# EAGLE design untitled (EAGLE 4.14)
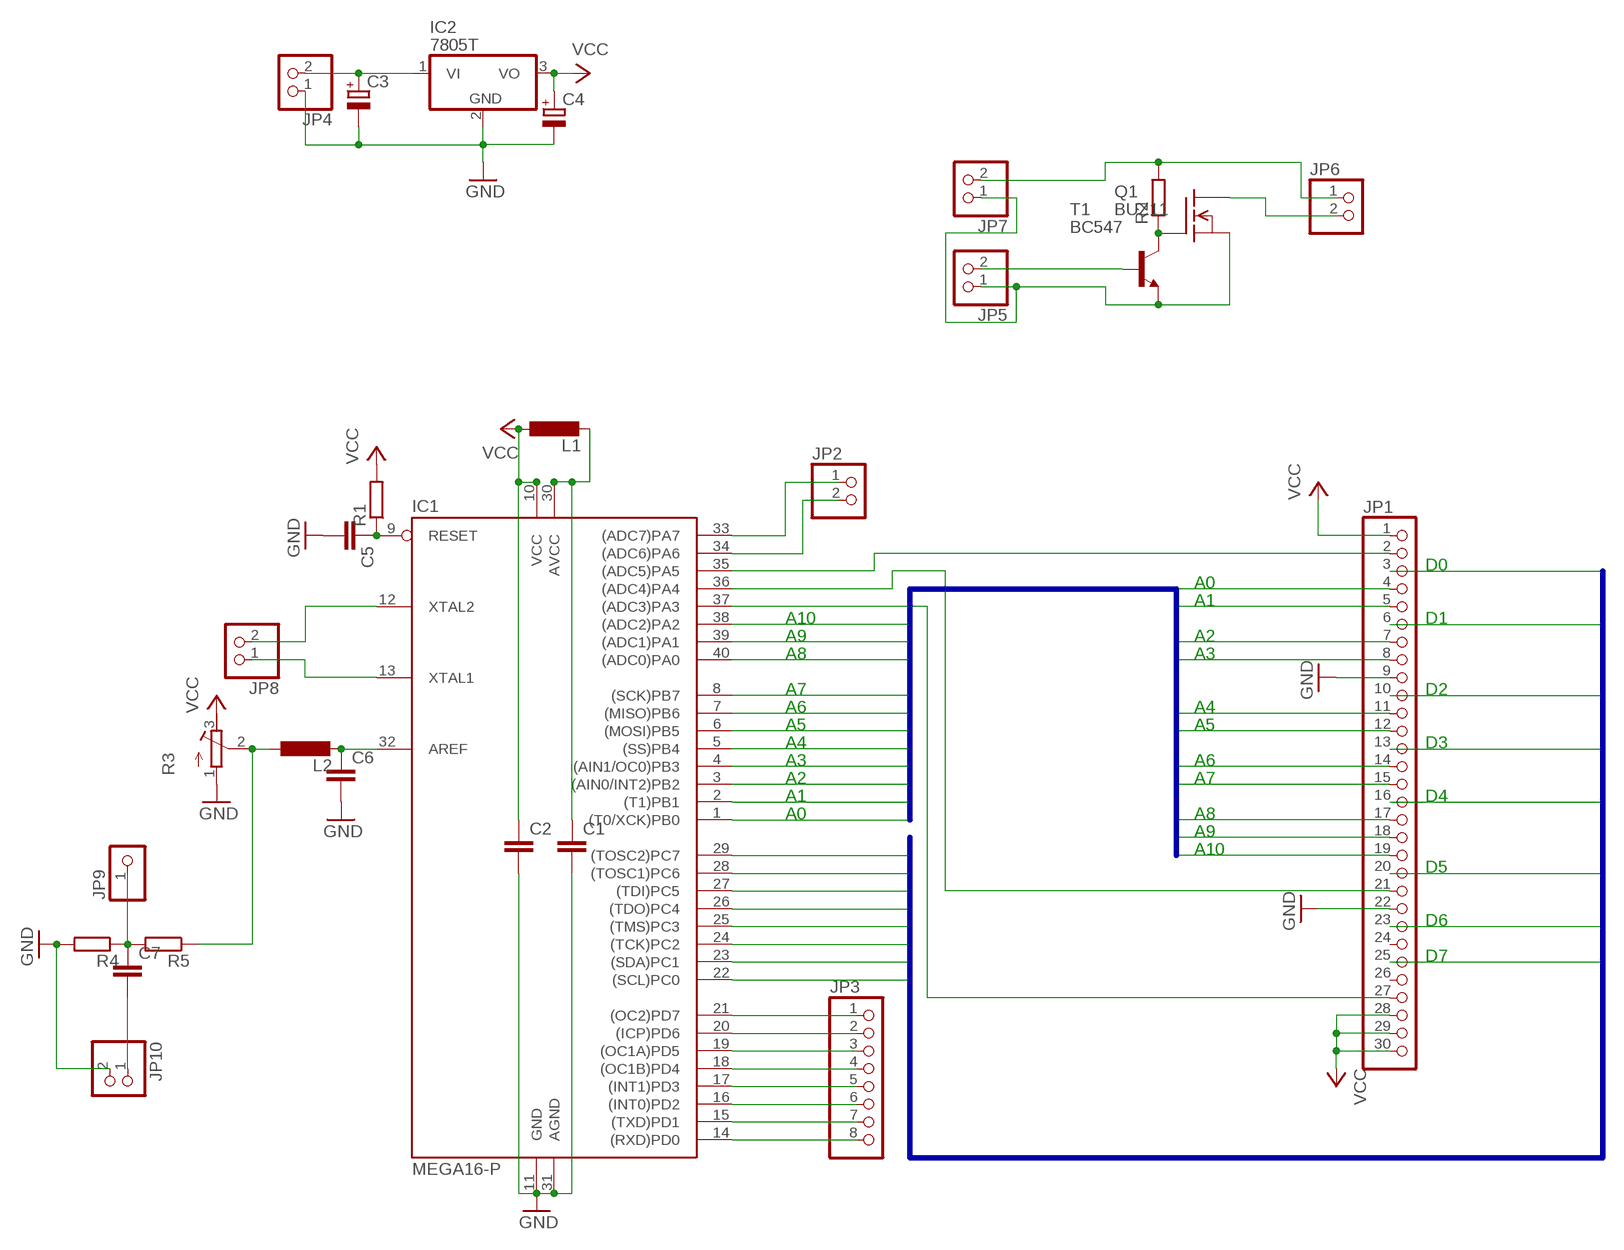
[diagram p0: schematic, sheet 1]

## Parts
C1  C-EU025-025X050  [C025-025X050]
C2  C-EU025-025X050  [C025-025X050]
C3  CPOL-EUE2-4  [E2-4]
C4  CPOL-EUE2-4  [E2-4]
C5  C-EU025-025X050  [C025-025X050]
C6  C-EU025-025X050  [C025-025X050]
C7  C-EU025-025X050  [C025-025X050]
IC1  MEGA16-P  [DIL40]
IC2  7805T  [TO220H]
JP1  PINHD-1X30  [1X30]
JP2  PINHD-1X2  [1X02]
JP3  PINHD-1X8  [1X08]
JP4  PINHD-1X2  [1X02]
JP5  PINHD-1X2  [1X02]
JP6  PINHD-1X2  [1X02]
JP7  PINHD-1X2  [1X02]
JP8  PINHD-1X2  [1X02]
JP9  PINHD-1X1  [1X01]
JP10  PINHD-1X2  [1X02]
L1  L-EUL3225M  [L3225M]
L2  L-EUL3225M  [L3225M]
Q1  BUZ11  [TO220]
R1  R-EU_0207/2V  [0207/2V]
R2  R-EU_0204/7  [0204/7]
R3  R-TRIMM3339P  [RTRIM3339P]
R4  R-EU_0204/7  [0204/7]
R5  R-EU_0204/7  [0204/7]
T1  BC547  [TO92]

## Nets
GND: C1.2 C2.2 C3.- C4.- C5.2 C6.2 IC1.11(GND) IC1.31(AGND) IC2.2(GND) JP1.9 JP1.22 JP4.1 JP10.2 R3.1(E) R4.2
N$1: IC1.22((SCL)PC0) JP1.3
N$2: IC1.23((SDA)PC1) JP1.6
N$3: IC1.24((TCK)PC2) JP1.10
N$4: IC1.25((TMS)PC3) JP1.13
N$5: IC1.26((TDO)PC4) JP1.16
N$6: IC1.27((TDI)PC5) JP1.20
N$7: IC1.28((TOSC1)PC6) JP1.23
N$8: IC1.29((TOSC2)PC7) JP1.25
N$9: IC1.1((T0/XCK)PB0) JP1.4
N$10: IC1.2((T1)PB1) JP1.5
N$11: IC1.3((AIN0/INT2)PB2) JP1.7
N$12: IC1.4((AIN1/OC0)PB3) JP1.8
N$13: IC1.5((SS)PB4) JP1.11
N$14: IC1.6((MOSI)PB5) JP1.12
N$15: IC1.7((MISO)PB6) JP1.14
N$16: IC1.8((SCK)PB7) JP1.15
N$17: IC1.40((ADC0)PA0) JP1.17
N$18: IC1.39((ADC1)PA1) JP1.18
N$19: IC1.38((ADC2)PA2) JP1.19
N$20: IC1.35((ADC5)PA5) JP1.2
N$21: IC1.36((ADC4)PA4) JP1.21
N$22: IC1.34((ADC6)PA6) JP2.2
N$23: IC1.37((ADC3)PA3) JP1.27
N$24: IC1.33((ADC7)PA7) JP2.1
N$25: IC1.21((OC2)PD7) JP3.1
N$26: IC1.20((ICP)PD6) JP3.2
N$27: IC1.19((OC1A)PD5) JP3.3
N$28: IC1.18((OC1B)PD4) JP3.4
N$29: IC1.17((INT1)PD3) JP3.5
N$30: IC1.16((INT0)PD2) JP3.6
N$31: JP6.1 JP7.2 R2.2
N$32: IC1.12(XTAL2) JP8.2
N$33: C1.1 IC1.30(AVCC) L1.2
N$34: JP6.2 Q1.2(D)
N$35: IC1.15((TXD)PD1) JP3.7
N$36: IC1.14((RXD)PD0) JP3.8
N$37: C3.+ IC2.1(VI) JP4.2
N$38: IC1.13(XTAL1) JP8.1
N$39: C5.1 IC1.9(RESET) R1.1
N$40: Q1.1(G) R2.1 T1.3(C)
N$41: JP5.2 T1.2(B)
N$42: JP5.1 JP7.1 Q1.3(S) T1.1(E)
N$43: C6.1 IC1.32(AREF) L2.2
N$44: L2.1 R3.2(S) R5.1
N$45: C7.1 JP9.1 R4.1 R5.2
N$46: C7.2 JP10.1
VCC: C2.1 C4.+ IC1.10(VCC) IC2.3(VO) JP1.1 JP1.28 JP1.29 JP1.30 L1.1 R1.2 R3.3(A)
Unconnected: JP1.24 JP1.26

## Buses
B$2
B$1

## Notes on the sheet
- D0
- A0
- A1
- A10 | D1
- A9 | A2
- A8 | A3
- A7 | D2
- A6 | A4
- A5 | A5
- A4 | D3
- A3 | A6
- A2 | A7
- A1 | D4
- A0 | A8
- A9
- A10
- D5
- D6
- D7

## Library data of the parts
C1 C2 C5-C7 = rcl:C-EU: CAPACITOR, European symbol
C3 C4 = rcl:CPOL-EU: POLARIZED CAPACITOR, European symbol
IC1 = atmel:MEGA16-P: MICROCONTROLLER 16 Kbytes FLASH 1 kbytes SRAM 512 bytes EEPROM USART 8-channel 10 bit ADC
IC2 = linear:78*: Positive VOLTAGE REGULATOR Source: http://cache.national.com/ds/LM/LM78L05.pdf http://www.fairchildsemi.com/ds/LM/LM7805.pdf
JP1 = pinhead:PINHD-1X30: PIN HEADER
JP2 JP4-JP8 JP10 = pinhead:PINHD-1X2: PIN HEADER
JP3 = pinhead:PINHD-1X8: PIN HEADER
JP9 = pinhead:PINHD-1X1: PIN HEADER
L1 L2 = rcl:L-EU: INDUCTOR, European symbol
Q1 = transistor-fet:BUZ11: N-Channel Enhancement MOSFET 50V; 30A; 0,040Ohm
R1 R2 R4 R5 = rcl:R-EU_: RESISTOR, European symbol
R3 = rcl:R-TRIMM: Trimm resistor
T1 = transistor:BC547: NPN TRANSISTOR

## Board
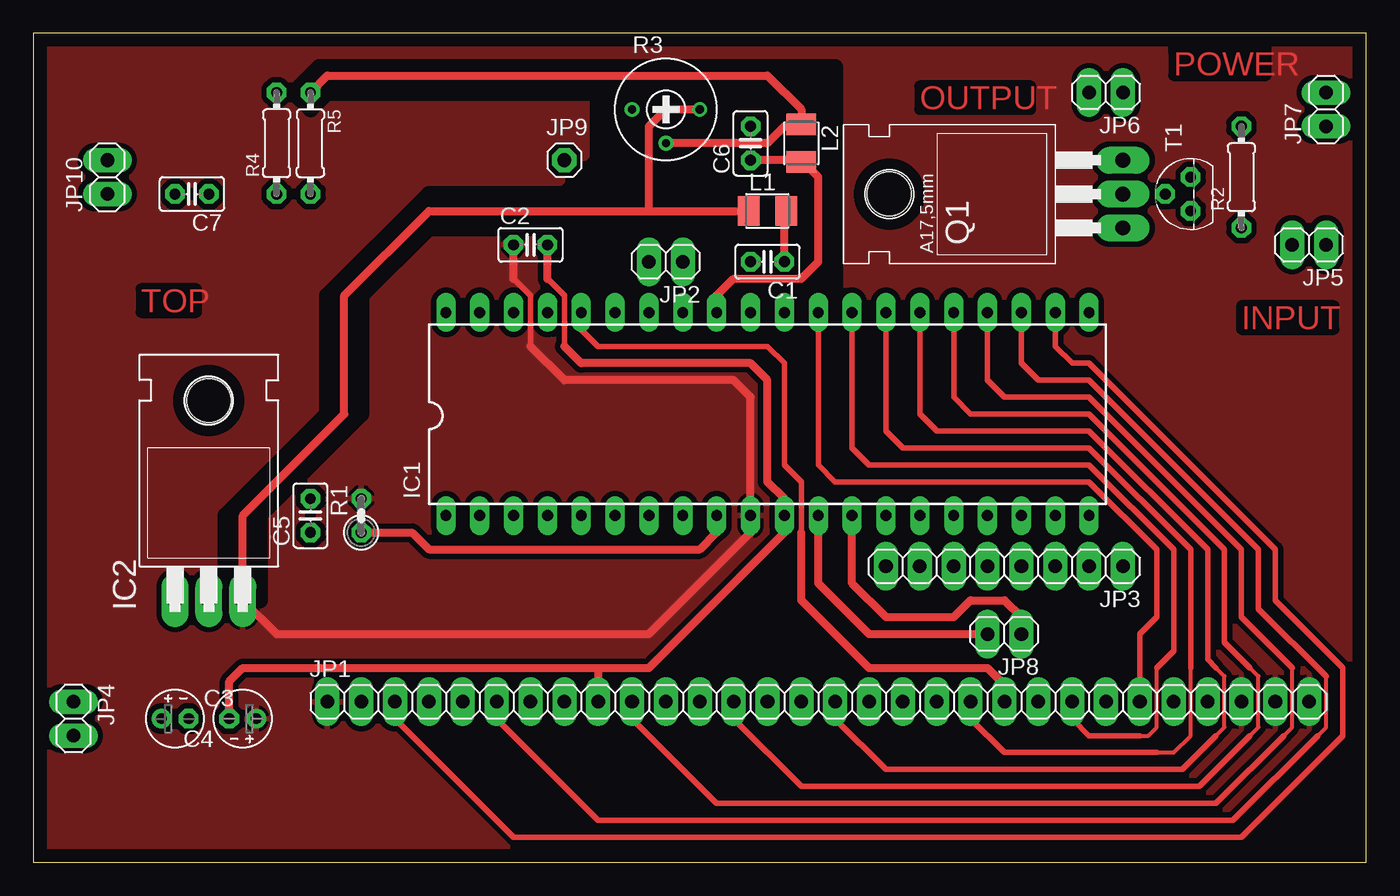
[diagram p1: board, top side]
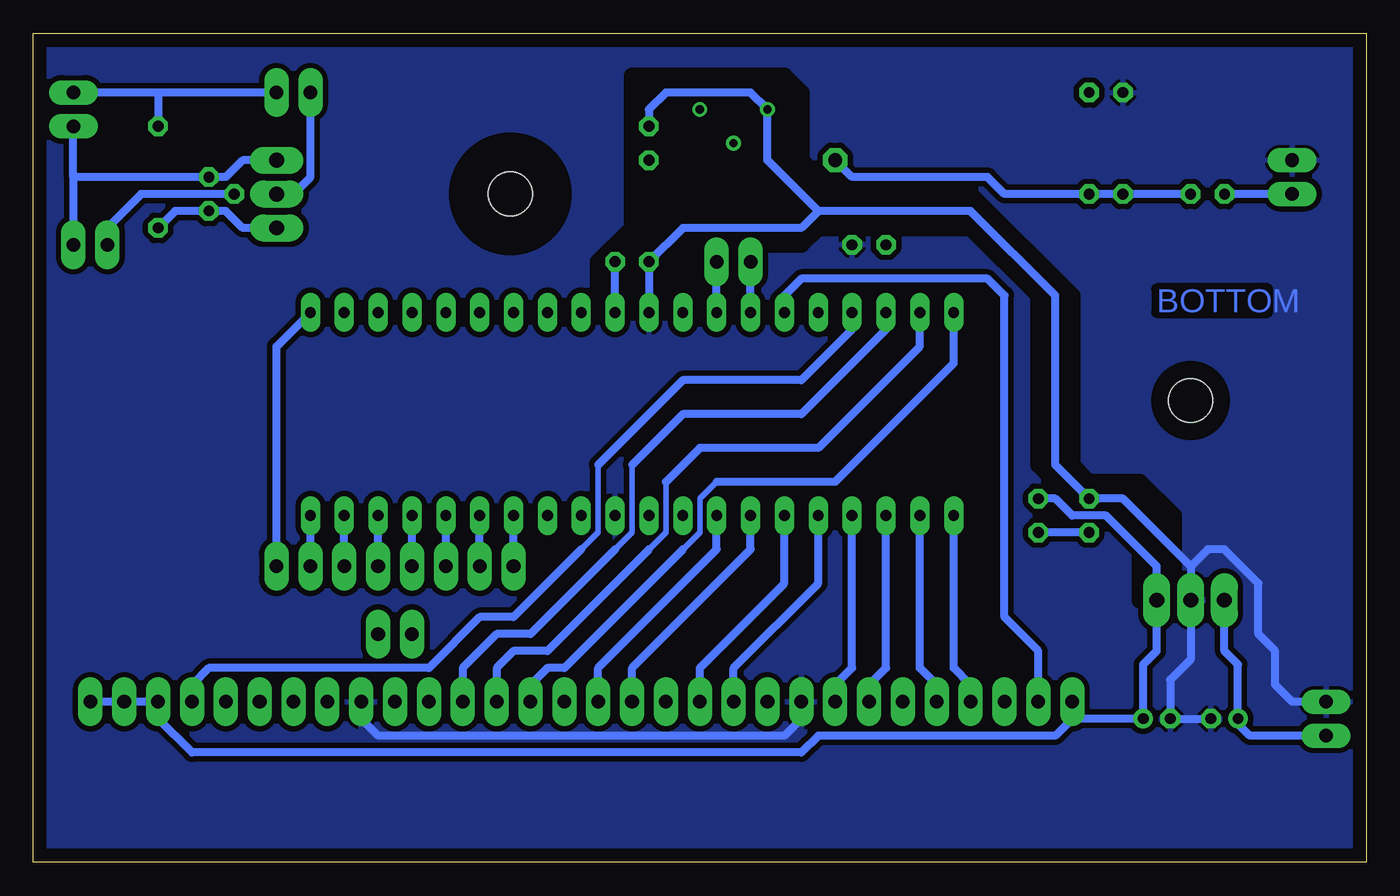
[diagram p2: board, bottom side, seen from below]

Size 100 x 62.22 mm. Coordinates in mm from the lower left corner, seen from the top.
Outline: 0,0 100,0 100,62.22 0,62.22 0,0
Copper layers (1*16): Top 0.035mm / dielectric 1.5mm / Bottom 0.035mm
Design rules "default": minimum track width 10mil, minimum drill 24mil, track to track 8mil, track to pad 8mil, pad to pad 8mil, via to via 8mil, smd to smd 8mil, copper to edge 40mil, drill to drill 8mil, minimum pad ring 10mil, minimum via ring 8mil, stop-mask expansion 4mil, vias tented up to drill 0mil, thermal gap 10mil
tRestrict: area 14.4,19.7 to 60.2,59.7; area 19.5,56.5 to 44.3,59.7
bRestrict: area 14.4,19.7 to 57.6,59.1

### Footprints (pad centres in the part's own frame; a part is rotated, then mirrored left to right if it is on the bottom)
C025-025X050 = drill 0.813 octagon: 1 -1.27,0; 2 1.27,0
E2-4 = drill 0.813 pad 1.27 round: + -1.016,0 | drill 0.813 pad 1.27 octagon: - 1.016,0
DIL40 = drill 0.813 long: 1 -24.13,-7.62; 2 -21.59,-7.62; 3 -19.05,-7.62; 4 -16.51,-7.62; 5 -13.97,-7.62; 6 -11.43,-7.62; 7 -8.89,-7.62; 8 -6.35,-7.62; 9 -3.81,-7.62; 10 -1.27,-7.62; 11 1.27,-7.62; 12 3.81,-7.62; 13 6.35,-7.62; 14 8.89,-7.62; 15 11.43,-7.62; 16 13.97,-7.62; 17 16.51,-7.62; 18 19.05,-7.62; 19 21.59,-7.62; 20 24.13,-7.62; 21 24.13,7.62; 22 21.59,7.62; 23 19.05,7.62; 24 16.51,7.62; 25 13.97,7.62; 26 11.43,7.62; 27 8.89,7.62; 28 6.35,7.62; 29 3.81,7.62; 30 1.27,7.62; 31 -1.27,7.62; 32 -3.81,7.62; 33 -6.35,7.62; 34 -8.89,7.62; 35 -11.43,7.62; 36 -13.97,7.62; 37 -16.51,7.62; 38 -19.05,7.62; 39 -21.59,7.62; 40 -24.13,7.62
TO220H = drill 1.118 long: 1 -2.54,-10.16; 2 0,-10.16; 3 2.54,-10.16 | hole 3.302: 0,4.826
1X30 = drill 1.016 long: 1 -36.83,0; 2 -34.29,0; 3 -31.75,0; 4 -29.21,0; 5 -26.67,0; 6 -24.13,0; 7 -21.59,0; 8 -19.05,0; 9 -16.51,0; 10 -13.97,0; 11 -11.43,0; 12 -8.89,0; 13 -6.35,0; 14 -3.81,0; 15 -1.27,0; 16 1.27,0; 17 3.81,0; 18 6.35,0; 19 8.89,0; 20 11.43,0; 21 13.97,0; 22 16.51,0; 23 19.05,0; 24 21.59,0; 25 24.13,0; 26 26.67,0; 27 29.21,0; 28 31.75,0; 29 34.29,0; 30 36.83,0
1X02 = drill 1.016 long: 1 -1.27,0; 2 1.27,0
1X08 = drill 1.016 long: 1 -8.89,0; 2 -6.35,0; 3 -3.81,0; 4 -1.27,0; 5 1.27,0; 6 3.81,0; 7 6.35,0; 8 8.89,0
1X01 = drill 1.016 octagon: 1 0,0
L3225M = smd 1.6 x 2.2: 1 -1.4,0; 2 1.4,0
TO220 = drill 1.118 long: 1 -2.54,-6.35; 2 0,-6.35; 3 2.54,-6.35 | hole 3.302: 0,11.176
0207/2V = drill 0.813 octagon: 1 -1.27,0; 2 1.27,0
0204/7 = drill 0.813 octagon: 1 -3.81,0; 2 3.81,0
RTRIM3339P = drill 0.61 round: 1 -2.54,0; 2 0,-2.54; 3 2.54,0
TO92 = drill 0.813 octagon: 1 1.27,0; 2 0,1.905; 3 -1.27,0

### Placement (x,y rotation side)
C1  55.08,45.08 180 top
C2  37.3,46.35 0 top
C3  10.63,10.79 0 top
C4  15.71,10.79 180 top
C5  20.79,26.03 90 top
C6  53.81,53.97 90 top
C7  11.9,50.16 180 top
IC1  55.08,33.65 0 top
IC2  13.17,29.84 0 top
JP1  58.89,12.06 0 top
JP2  47.46,45.08 180 top
JP3  72.86,22.22 180 top
JP4  3.01,10.79 270 top
JP5  95.72,46.35 180 top
JP6  80.48,57.78 180 top
JP7  96.99,56.51 90 top
JP8  72.86,17.14 180 top
JP9  39.84,52.7 0 top
JP10  5.55,51.43 90 top
L1  55.08,48.89 0 top
L2  57.62,53.97 270 top
Q1  75.4,50.16 90 top
R1  24.6,26.03 90 top
R2  90.64,51.43 90 top
R3  47.46,56.51 0 top
R4  18.25,53.97 90 top
R5  20.79,53.97 270 top
T1  86.83,50.16 90 top

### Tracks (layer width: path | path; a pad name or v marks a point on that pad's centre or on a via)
GND
  Top 0.406: 39.84,38.73 39.84,42.54 38.57,43.81
  Top 0.61: C4.- 14.69,13.58 15.71,14.6 42.38,14.6 | 39.84,38.73 41.11,37.46 53.81,37.46 55.08,36.19 55.08,28.57 56.35,27.3 IC1.11 56.35,24.76 46.19,14.6 42.38,14.6 | 38.57,43.81 C2.2 | 42.38,14.6 JP1.9
  Bottom 0.61: JP1.22 75.4,10.79 74.13,9.52 43.65,9.52 42.38,10.79 JP1.9 | C3.- C4.- 14.69,13.71 13.17,15.24 IC2.2 13.17,22.22 | JP4.1 5.55,12.06 6.82,13.33 6.82,15.87 8.09,17.14 8.09,20.95 10.63,23.49 11.9,23.49 13.17,22.22 | C1.2 IC1.31 C1.2 | 13.17,22.22 18.25,27.3 C5.2 23.33,29.84 23.33,42.54 29.68,48.89 41.11,48.89 | C1.2 51.27,47.62 42.38,47.62 41.11,48.89 | C6.2 53.81,56.51 52.54,57.78 46.19,57.78 R3.1 44.92,52.7 41.11,48.89
  pour Bottom (isolate 0.406): 99.53,61.59 0.47,61.59 0.47,0.63 99.53,0.63
N$1
  Top 0.406: IC1.22 76.67,38.73 77.94,37.46 79.21,37.46 93.18,23.49 93.18,19.68 98.26,14.6 98.26,9.52 90.64,1.9 36.03,1.9 27.14,10.79 JP1.3
N$2
  Top 0.305: 96.99,13.97 96.99,10.16 96.36,9.52
  Top 0.406: IC1.23 74.13,37.46 75.4,36.19 79.21,36.19 91.91,23.49 91.91,19.04 96.99,13.97 | JP1.6 34.76,10.79 42.38,3.17 90,3.17 96.36,9.52
N$3
  Top 0.305: 94.45,14.6 94.45,10.16 93.81,9.52
  Top 0.406: IC1.24 71.59,36.19 72.86,34.92 79.21,34.92 90.64,23.49 90.64,18.41 94.45,14.6 | JP1.10 44.92,10.79 51.27,4.44 88.73,4.44 93.81,9.52
N$4
  Top 0.305: 91.28,14.6 91.91,13.97 91.91,10.16 91.28,9.52
  Top 0.406: IC1.25 69.05,34.92 70.32,33.65 79.21,33.65 89.37,23.49 89.37,16.5 91.28,14.6 | JP1.13 52.54,10.79 57.62,5.71 87.47,5.71 91.28,9.52
N$5
  Top 0.305: 88.73,14.6 89.37,13.97 89.37,10.16 88.73,9.52
  Top 0.406: IC1.26 66.51,33.65 67.78,32.38 79.21,32.38 88.1,23.49 88.1,15.24 88.73,14.6 | JP1.16 60.16,10.79 63.97,6.98 86.19,6.98 88.73,9.52
N$6
  Top 0.305: 86.83,14.6 86.83,9.52 85.56,8.25 84.29,8.25
  Top 0.406: IC1.27 63.97,32.38 65.24,31.11 79.21,31.11 86.83,23.49 86.83,14.6 | 84.29,8.25 72.86,8.25 70.32,10.79 JP1.20
N$7
  Top 0.305: 84.29,14.6 84.29,10.16 83.66,9.52 83.02,9.52
  Top 0.406: IC1.28 61.43,31.11 62.7,29.84 79.21,29.84 85.56,23.49 85.56,15.87 84.29,14.6 | 83.02,9.52 79.21,9.52 77.94,10.79 JP1.23
N$8
  Top 0.406: IC1.29 58.89,29.84 60.16,28.57 79.21,28.57 84.29,23.49 84.29,18.41 83.02,17.14 JP1.25
N$9
  Bottom 0.61: IC1.1 30.95,14.6 29.68,13.33 JP1.4
N$10
  Bottom 0.61: IC1.2 33.49,14.6 32.22,13.33 JP1.5
N$11
  Bottom 0.61: IC1.3 36.03,14.6 37.3,13.33 JP1.7
N$12
  Bottom 0.61: IC1.4 38.57,14.6 39.84,13.33 JP1.8
N$13
  Bottom 0.61: IC1.5 41.11,20.95 47.46,14.6 JP1.11
N$14
  Bottom 0.61: IC1.6 43.65,20.95 50,14.6 JP1.12
N$15
  Bottom 0.61: IC1.7 46.19,23.49 55.08,14.6 JP1.14
N$16
  Bottom 0.61: IC1.8 48.73,23.49 57.62,14.6 JP1.15
N$17
  Bottom 0.406: 48.73,28.57 50,27.3 50,24.76 51.27,23.49
  Bottom 0.61: IC1.40 30.95,37.46 39.84,28.57 48.73,28.57 | JP1.17 62.7,13.33 61.43,14.6 60.16,14.6 51.27,23.49
N$18
  Bottom 0.406: 52.54,28.57 52.54,24.76 53.81,23.49
  Bottom 0.61: IC1.39 33.49,38.73 41.11,31.11 50,31.11 52.54,28.57 | JP1.18 65.24,14.6 63.97,15.87 61.43,15.87 53.81,23.49
N$19
  Bottom 0.406: 55.08,29.84 55.08,24.76 56.35,23.49
  Bottom 0.61: IC1.38 36.03,40 42.38,33.65 51.27,33.65 55.08,29.84 | JP1.19 67.78,14.6 65.24,17.14 62.7,17.14 56.35,23.49
N$20
  Bottom 0.61: IC1.35 43.65,42.54 42.38,43.81 28.41,43.81 27.14,42.54 27.14,18.41 24.6,15.87 JP1.2
N$21
  Top 0.406: IC1.36 41.11,40 42.38,38.73 55.08,38.73 56.35,37.46 56.35,29.84 57.62,28.57 57.62,24.76 | 72.86,13.33 JP1.21
  Top 0.61: 57.62,24.76 57.62,19.68 62.7,14.6 71.59,14.6 72.86,13.33
N$22
  Bottom 0.61: IC1.34 JP2.2
N$23
  Bottom 0.406: 57.62,29.84 57.62,24.76 58.89,23.49
  Bottom 0.61: JP1.27 88.1,13.33 86.83,14.6 70.32,14.6 66.51,18.41 63.97,18.41 58.89,23.49 | 57.62,29.84 51.27,36.19 42.38,36.19 38.57,40 IC1.37
N$24
  Bottom 0.61: IC1.33 JP2.1
N$25
  Bottom 0.61: JP3.1 81.75,38.73 IC1.21
N$26
  Bottom 0.61: JP3.2 IC1.20
N$27
  Bottom 0.61: JP3.3 IC1.19
N$28
  Bottom 0.61: JP3.4 IC1.18
N$29
  Bottom 0.61: JP3.5 IC1.17
N$30
  Bottom 0.61: JP3.6 IC1.16
N$31
  Bottom 0.61: 90.64,57.78 JP7.2 | 90.64,57.78 R2.2 | JP6.1 90.64,57.78
N$32
  Top 0.61: JP8.2 62.7,17.14 58.89,20.95 IC1.12
N$33
  Top 0.61: L1.2 56.35,48.89 C1.1
  Bottom 0.61: IC1.30 C1.1
N$34
  Bottom 0.61: Q1.2 80.48,50.16 79.21,51.43 JP6.2
N$35
  Bottom 0.61: JP3.7 IC1.15
N$36
  Bottom 0.61: JP3.8 IC1.14
N$37
  Bottom 0.61: 10.63,19.04 IC2.1 10.63,15.87 9.61,14.85 C3.+ 9.61,10.41 8.73,9.52 JP4.2
N$38
  Top 0.61: JP8.1 74.13,18.41 72.86,19.68 70.32,19.68 69.05,18.41 63.97,18.41 61.43,20.95 IC1.13
N$39
  Top 0.61: R1.1 28.41,24.76 29.68,23.49 50,23.49 51.27,24.76 IC1.9
  Bottom 0.61: C5.1 R1.1
N$40
  Bottom 0.61: Q1.1 84.29,47.62 85.56,48.89 T1.3 89.37,48.89 R2.1
N$41
  Bottom 0.61: T1.2 91.91,50.16 94.45,47.62 JP5.2
N$42
  Bottom 0.61: Q1.3 84.29,52.7 85.56,51.43 T1.1 96.99,51.43 | 96.99,51.43 JP5.1 | 96.99,51.43 JP7.1
N$43
  Top 0.61: IC1.32 51.27,42.54 52.54,43.81 57.62,43.81 58.89,45.08 58.89,51.43 57.75,52.57 L2.2 57.62,52.7 C6.1
N$44
  Top 0.61: 57.62,55.24 L2.1 | R3.2 55.08,53.97 56.35,55.24 57.62,55.24 | 57.62,55.24 57.62,56.51 55.08,59.05 22.06,59.05 R5.1
N$45
  Bottom 0.61: C7.1 R4.1 R5.2 27.14,50.16 28.41,51.43 38.57,51.43 JP9.1
N$46
  Bottom 0.61: JP10.1 C7.2
VCC
  Top 0.406: 37.3,38.73 37.3,42.54 36.03,43.81
  Top 0.61: 37.3,38.73 39.84,36.19 52.54,36.19 53.81,34.92 IC1.10 53.81,24.76 46.19,17.14 18.25,17.14 IC2.3 15.71,26.03 23.33,33.65 23.33,42.54 29.68,48.89 46.19,48.89 | 36.03,43.81 C2.1 | 46.19,48.89 L1.1 | R3.3 47.46,56.51 46.19,55.24 46.19,48.89
  Bottom 0.61: 22.06,10.79 JP1.1 | JP1.30 JP1.29 JP1.28 90.64,10.79 88.1,8.25 42.38,8.25 41.11,9.52 23.33,9.52 22.06,10.79 | 22.06,10.79 C4.+ 16.73,14.85 15.71,15.87 IC2.3 15.71,22.22 19.52,26.03 22.06,26.03 23.33,27.3 R1.2
  pour Top (isolate 0.406): 99.53,61.59 0.47,61.59 0.47,0.63 99.53,0.63

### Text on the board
Top: POWER | OUTPUT | TOP | INPUT
Bottom: BOTTOM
